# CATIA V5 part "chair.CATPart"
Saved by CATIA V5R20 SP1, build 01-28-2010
Part number: Part1
Bounding box of the stored display mesh (mm): x -251 to 251, y -23.502 to 607.363, z -74.572 to 451.098
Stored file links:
  J:\hosseini\chair.CATPart
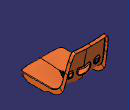
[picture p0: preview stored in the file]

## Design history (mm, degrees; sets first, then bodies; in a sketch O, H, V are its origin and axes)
Body1 (main body)
  Sketch1 on xy-plane, origin (0, 0, 0), H (1, 0, 0), V (0, 1, 0)
    point P1 (209.612, 569.9541)
    line L1 (221.6025, 549.1858) -> (236.6025, 523.2051)
    point P2 (250, 500)
    line L2 (250, 473.2051) -> (250, 33.8088)
    point P3 (250, 0)
    point P4 (-250, 500)
    point P5 (-209.612, 569.9541)
    line L3 (-221.6025, 549.1858) -> (-236.6025, 523.2051)
    point P6 (-250, 0)
    line L4 (-250, 473.2051) -> (-250, 33.8088)
    arc A1 centre (0, 6566.2916) radius 6000 from (185.7234, 569.1667) to (-185.7234, 569.1667) cw
    point P8 (0, 566.2916)
    arc A2 centre (186.9615, 529.1858) radius 40 from (185.7234, 569.1667) to (221.6025, 549.1858) cw
    arc A3 centre (150, 473.2051) radius 100 from (236.6025, 523.2051) to (250, 473.2051) cw
    arc A4 centre (-186.9615, 529.1858) radius 40 from (-185.7234, 569.1667) to (-221.6025, 549.1858) ccw
    arc A5 centre (-150, 473.2051) radius 100 from (-236.6025, 523.2051) to (-250, 473.2051) ccw
    arc A6 centre (0, 1377.4977) radius 1400 from (216.1765, -5.7115) to (-216.1765, -5.7115) cw
    point P22 (0, -22.5023)
    arc A7 centre (-210, 33.8088) radius 40 from (-216.1765, -5.7115) to (-250, 33.8088) cw
    arc A8 centre (210, 33.8088) radius 40 from (216.1765, -5.7115) to (250, 33.8088) ccw
    distance L2 L4 = 500
    radius A1 = 6000
    radius A2 = 40
    distance P2 P3 = 500
    radius A3 = 100
    radius A4 = 40
    radius A5 = 100
    length L1 = 30
    angle L1 L2 = 150
    radius A7 = 40
    radius A8 = 40
    radius A6 = 1400
    vertical: L2 V
    symmetry: P2 P4 V, P1 P5 V, L1 L3 V, P3 P6 V, L2 L4 V
    coincidence: A1 P8, P8 V, A1 P1, L1 P1, L1 P2, L2 P2, A1 P5, L3 P5, L3 P4, L4 P4, H P3, A6 P22, P22 V, A6 P6, L4 P6, A6 P3, L2 P3
    tangency: A2 L1, A2 A1, A3 L1, A3 L2, A4 L3, A4 A1, A5 L3, A5 L4, A7 L4, A7 A6, A8 L2, A8 A6
  Fill1: Boundary Sketch1
  Sketch2 on xy-plane, origin (0, 0, 0), H (1, 0, 0), V (0, 1, 0)
    line L1 (0, -57.8765) -> (0, 586.2175)
    point P1 (0, -57.8765)
    point P2 (0, 586.2175)
    coincidence: P1 V
    vertical: L1 V
  Sketch3 on yz-plane, origin (0, 0, 0), H (0, 1, 0), V (0, 0, 1)
    point P1 (-57.8765, 0)
    line L1 (-57.8765, 0) -> (352.4618, 0)
    line L2 (499.2411, 119.0834) -> (586.2175, 532.0119)
    point P2 (586.2175, 532.0119)
    arc A1 centre (352.4618, 150) radius 150 from (352.4618, 0) to (499.2411, 119.0834) ccw
    reference projected point E1 (586.2175, 0) from Sketch2.P2
    reference projected point E2 (-57.8765, 0) from Sketch2.P1
    radius A1 = 150
    distance P2 E1 H = 0
    coincidence: P1 H, P1 E2
    horizontal: L1 H
    tangency: A1 L1, A1 L2
  GSOWrapCurve1: SurfaceToDeform Fill1
  Boundary1: Boundary edge of Fill1
  Plane1: type Normal, Curve Boundary1, RefPoint vertex [face of Fill1 | face of Fill1]
  Point1: (0, 0, 0), relative to vertex [face of Fill1 | face of Fill1]
  Sketch4 on Plane1, origin (0, 33.8088, 0), H (-1, 0, 0), V (0, 0, 1)
    line L1 (-250, 0) -> (-250, -90)
    point P1 (-250, 0)
    reference projected point E1 (-250, 0) from Point1
    length L1 = 90
    coincidence: P1 H, E1 P1
    vertical: L1 V
  Sketch5 on yz-plane, origin (0, 0, 0), H (0, 1, 0), V (0, 0, 1)
    arc A1 centre (358.0075, 133.522) radius 157.853 from (515.8095, 129.5102) to (344.7389, -23.7724) cw
    line L1 (344.7389, -23.7724) -> (65.2078, -0.1925)
    arc A2 centre (60.6357, -54.3925) radius 54.3925 from (65.2078, -0.1925) to (60.6357, 0) ccw
    line L2 (60.6357, 0) -> (-57.8765, 0)
    point P7 (-57.8765, 0)
    reference projected point E1 (-57.8765, 0) from Sketch3.P1
    arc A3 centre (1365.3494, 107.9122) radius 849.8143 from (515.8095, 129.5102) to (533.7816, 283.0679) cw
    line L3 (533.7816, 283.0679) -> (586.2175, 532.0119)
    point P10 (586.2175, 532.0119)
    reference projected line E2 (499.2411, 119.0834) -> (586.2175, 532.0119) from Sketch3.L2
    reference projected point E3 (586.2175, 532.0119) from Sketch3.P2
    tangency: L1 A1, A2 L1, L2 A2, L3 A3, A3 A1
    horizontal: L2 H
    coincidence: E1 P7, P10 E3
    parallelism: E2 L3
  Point2: (0, 0, 0)
  Line1: type Normal, RefPoint Point2, RefSkin yz-plane, Start 0, End -354
  Plane2: type Angle, RefPlane zx-plane, Direction Line1, Angle -45
  Plane3: type Offset, RefPlane Plane2, Offset 223, reversed
  Sketch6 on Plane3, origin (0, -157.6848, 157.6848), H (-1, 0, 0), V (0, 0.7071, 0.7071)
    line L1 (-191.9214, 775.8616) -> (-191.9214, 454.495)
    arc A1 centre (-207.2605, 454.495) radius 15.3391 from (-191.9214, 454.495) to (-197.1559, 442.9545) cw
    line L2 (-197.1559, 442.9545) -> (-221.7033, 421.4613)
    arc A2 centre (-200.3983, 397.1287) radius 32.3416 from (-221.7033, 421.4613) to (-232.7399, 397.1287) ccw
    line L3 (-232.7399, 397.1287) -> (-232.7399, -94.751)
    vertical: L1 V, L3 V
    tangency: A1 L1, L2 A1, A2 L2, L3 A2
  Project1: ToProject Sketch6, Support GSOWrapCurve1, Direction Plane3
  Symmetry1: Reference yz-plane, ToTransfor Project1
  GSOWrapCurve2: SurfaceToDeform GSOWrapCurve1
  Sweep1: type Unspec, Profile Sketch4, Guide Boundary1
  Sketch7 on yz-plane, origin (0, 0, 0), H (0, 1, 0), V (0, 0, 1)
    line L1 (626.0718, 532.0526) -> (531.3403, 82.3061)
    arc A1 centre (371.746, 115.9219) radius 163.0963 from (531.3403, 82.3061) to (371.746, -47.1743) cw
    line L2 (371.746, -47.1743) -> (342.9278, -47.1743)
    reference projected line E1 (499.2411, 119.0834) -> (586.2175, 532.0119) from Sketch3.L2
    line L3 (330.9665, -51.1454) -> (299.5731, -74.5722)
    line L4 (299.5731, -74.5722) -> (90.1214, -74.5722)
    arc A2 centre (17.3116, -132.3877) radius 92.9725 from (90.1214, -74.5722) to (17.3116, -39.4152) ccw
    arc A3 centre (342.9278, -67.1743) radius 20 from (342.9278, -47.1743) to (330.9665, -51.1454) ccw
    line L5 (17.3116, -39.4152) -> (-99.352, -39.4152)
    radius A3 = 20
    length L2 = 28.8181
    tangency: A1 L1, L2 A1, A3 L2, A3 L3, L5 A2
    horizontal: L2 H, L4 H, L5 H
    parallelism: L1 E1
  Join1: Elements (Sweep1; GSOWrapCurve2)
  Intersect1: ToIntersect1 yz-plane, ToIntersect2 Boundary1
  Near1: MultiElement Intersect1, ReferenceElement Point1
  Point3: (0, 0, 0), relative to vertex [face of Sweep1 | face of Sweep1 | face of Fill1]
  Point4: (0, 0, 0), relative to vertex [face of Fill1 | face of Sweep1 | face of Sweep1]
  Split1: ToCut Join1, Cutting yz-plane
  Fillet1: on edge [face of Sweep1 | face of Fill1]
  Extrude1: Element1 Sketch7, Lim1 450, Lim2 0
  Split2: ToCut Fillet1, Cutting Extrude1
  Sketch8 on Plane3, origin (0, -157.6848, 157.6848), H (-1, 0, 0), V (0, 0.7071, 0.7071)
    point P1 (-185.8796, 512.1897)
    line L1 (-185.8796, 505.5083) -> (-185.8796, 457.5778)
    point P2 (-185.8796, 452.1897)
    line L2 (-180.5226, 451.6123) -> (-145.2135, 447.8065)
    point P3 (-140.1445, 447.2601)
    arc A1 centre (-190.0871, 480.5127) radius 60 from (-137.3206, 451.9523) to (-134.1731, 502.2754) ccw
    point P5 (-136.1675, 506.8314)
    line L3 (-140.7709, 507.3276) -> (-179.2366, 511.4737)
    arc A2 centre (-141.6283, 499.3737) radius 8 from (-134.1731, 502.2754) to (-140.7709, 507.3276) ccw
    arc A3 centre (-144.3561, 455.7604) radius 8 from (-137.3206, 451.9523) to (-145.2135, 447.8065) cw
    arc A4 centre (-179.8796, 505.5083) radius 6 from (-179.2366, 511.4737) to (-185.8796, 505.5083) ccw
    arc A5 centre (-179.8796, 457.5778) radius 6 from (-185.8796, 457.5778) to (-180.5226, 451.6123) ccw
    distance P5 P1 = 50
    radius A2 = 8
    distance P2 P3 = 46
    radius A3 = 8
    radius A1 = 60
    distance P1 P2 = 60
    radius A4 = 6
    radius A5 = 6
    vertical: L1 V
    parallelism: L3 L2
    coincidence: A1 P5, L3 P5, A1 P3, L2 P3, L3 P1, L1 P1, L1 P2, L2 P2
    tangency: A2 A1, A2 L3, A3 L2, A3 A1, A4 L3, A4 L1, A5 L1, A5 L2
  Project2: ToProject Sketch8, Support Split2, Direction Plane3
  Sketch9 on yz-plane, origin (0, 0, 0), H (0, 1, 0), V (0, 0, 1)
    line L1 (534.0734, 212.2182) -> (486.0953, 25.7536)
  Extrude2: Element1 Sketch9, Lim1 450, Lim2 450
  GSOWrapCurve3: SurfaceToDeform Extrude2
  Extrude3: Element1 Project2, Lim1 523, Lim2 8, Direction Plane3, FirstUpto GSOWrapCurve3
  Sketch10 on Plane3, origin (0, -157.6848, 157.6848), H (-1, 0, 0), V (0, 0.7071, 0.7071)
    arc A1 centre (0, 714.5433) radius 220 from (-62.7193, 503.6729) to (0, 494.5433) ccw
    point P1 (0, 714.5433)
    point P2 (0, 494.5433)
    arc A2 centre (-27.8906, 476.3354) radius 50 from (-72.0685, 499.7515) to (-72.5882, 453.9273) ccw
    arc A3 centre (0, 637.4308) radius 200 from (-66.9986, 448.9867) to (0, 437.4308) ccw
    point P4 (0, 637.4308)
    point P5 (0, 437.4308)
    arc A4 centre (-65, 496.0049) radius 8 from (-62.7193, 503.6729) to (-72.0685, 499.7515) ccw
    point P6 (-62.7193, 503.6729)
    point P7 (-72.0685, 499.7515)
    point P8 (-65, 496.0049)
    arc A5 centre (-63.6487, 458.4089) radius 10 from (-66.9986, 448.9867) to (-72.5882, 453.9273) cw
    point P9 (-66.9986, 448.9867)
    point P10 (-72.5882, 453.9273)
    reference projected line E1 (0, 527.7079) -> (0, 361.9318) from Sketch9
    point P12 (0, 494.5433)
    point P14 (0, 437.4308)
    point P15 (62.7193, 503.6729)
    point P16 (72.0685, 499.7515)
    point P18 (66.9986, 448.9867)
    point P19 (72.5882, 453.9273)
    arc A6 centre (0, 714.5433) radius 220 from (62.7193, 503.6729) to (0, 494.5433) cw
    arc A7 centre (27.8906, 476.3354) radius 50 from (72.0685, 499.7515) to (72.5882, 453.9273) cw
    arc A8 centre (0, 637.4308) radius 200 from (66.9986, 448.9867) to (0, 437.4308) cw
    arc A9 centre (65, 496.0049) radius 8 from (62.7193, 503.6729) to (72.0685, 499.7515) cw
    arc A10 centre (63.6487, 458.4089) radius 10 from (66.9986, 448.9867) to (72.5882, 453.9273) ccw
    radius A4 = 8
    radius A5 = 10
    radius A1 = 220
    radius A3 = 200
    radius A2 = 50
    distance P8 E1 = 65
    coincidence: P1 V, P2 V, P4 V, P5 V
    tangency: A4 A1, A4 A2, A5 A3, A5 A2
    symmetry: P2 P12 V, P5 P14 V, P6 P15 V, P7 P16 V, P9 P18 V, P10 P19 V, A1 A6 V, A2 A7 V, A3 A8 V, A4 A9 V, A5 A10 V
  Symmetry2: Reference yz-plane, ToTransfor Split2
  Symmetry3: Reference yz-plane, ToTransfor Extrude3
  Join2: Elements (Split2; Symmetry2)
  Fillet2: type BiTangent, Element1 Extrude3, Element2 Join2, Radius 4
  Fillet3: type BiTangent, Element1 Fillet2, Element2 Symmetry3, Radius 4
  Extrude4: Element1 Sketch10, Lim1 523, Lim2 8, FirstUpto GSOWrapCurve3
  Fillet4: type BiTangent, Element1 Extrude4, Element2 Fillet3, Radius 4
  Plane4: type Offset, RefPlane xy-plane, Offset 165
  Sketch11 on Plane4, origin (0, 0, 165), H (1, 0, 0), V (0, 1, 0)
    circle A1 centre (0, 313.5888) radius 7.5
    point P1 (0, 313.5888)
    point P2 (0, 306.0888)
    radius A1 = 7.5
    coincidence: P1 V, A1 P2, P2 V
  Extrude5: Element1 Sketch11, Lim1 191, Lim2 8
  Translate1: ToTransfor Extrude5, Direction (1, 0, 0), Length 20
  Translate2: ToTransfor Extrude5, Direction (1, 0, 0), Length 40
  Translate3: ToTransfor Extrude5, Direction (1, 0, 0), Length -20
  Translate4: ToTransfor Extrude5, Direction (1, 0, 0), Length -40
  Translate5: ToTransfor Extrude5, Direction (0, 1, 0), Length -20
  Translate6: ToTransfor Translate5, Direction (1, 0, 0), Length -10
  Translate7: ToTransfor Translate6, Direction (1, 0, 0), Length -20
  Translate8: ToTransfor Translate6, Direction (1, 0, 0), Length 20
  Translate9: ToTransfor Translate6, Direction (1, 0, 0), Length 40
  Translate10: ToTransfor Extrude5, Direction (0, 1, 0), Length -40
  Translate11: ToTransfor Translate10, Direction (1, 0, 0), Length 20
  Translate12: ToTransfor Translate10, Direction (1, 0, 0), Length -20
  Translate13: ToTransfor Translate8, Direction (0, 1, 0), Length -40
  Translate14: ToTransfor Translate6, Direction (0, 1, 0), Length -40
  Translate15: ToTransfor Translate10, Direction (0, 1, 0), Length -40
  Fillet5: type BiTangent, Element1 Fillet4, Element2 Translate2, Radius 1
  Fillet6: type BiTangent, Element1 Fillet5, Element2 Translate1, Radius 1
  Fillet7: type BiTangent, Element1 Fillet6, Element2 Extrude5, Radius 1
  Fillet8: type BiTangent, Element1 Fillet7, Element2 Translate3, Radius 1
  Fillet9: type BiTangent, Element1 Fillet8, Element2 Translate4, Radius 1
  Fillet10: type BiTangent, Element1 Fillet9, Element2 Translate9, Radius 1
  Fillet11: type BiTangent, Element1 Fillet10, Element2 Translate8, Radius 1
  Fillet12: type BiTangent, Element1 Fillet11, Element2 Translate6, Radius 1
  Fillet13: type BiTangent, Element1 Fillet12, Element2 Translate7, Radius 1
  Fillet14: type BiTangent, Element1 Fillet13, Element2 Translate11, Radius 1
  Fillet15: type BiTangent, Element1 Fillet14, Element2 Translate10, Radius 1
  Fillet16: type BiTangent, Element1 Fillet15, Element2 Translate12, Radius 1
  Fillet17: type BiTangent, Element1 Fillet16, Element2 Translate13, Radius 1
  Fillet18: type BiTangent, Element1 Fillet17, Element2 Translate14, Radius 1
  Fillet19: type BiTangent, Element1 Fillet18, Element2 Translate15, Radius 1
  ThickSurface1: Surface Fillet19, TopOffset 1, BotOffset 1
